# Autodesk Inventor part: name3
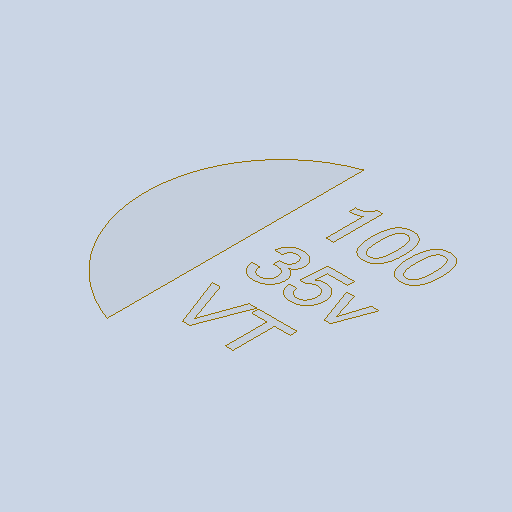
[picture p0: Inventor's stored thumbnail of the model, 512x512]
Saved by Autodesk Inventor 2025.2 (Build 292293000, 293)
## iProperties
Created: 2025-04
Part Number: name3
Material: Generic
Description: PART--DESC
Document SubType Name: Modeling
Designer: BennF
Density: 1 g/cm^3
Appearance: Default
Author: BennF
Revision Number: NONE
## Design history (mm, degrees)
feature "Composite1"
body "Srf1"
